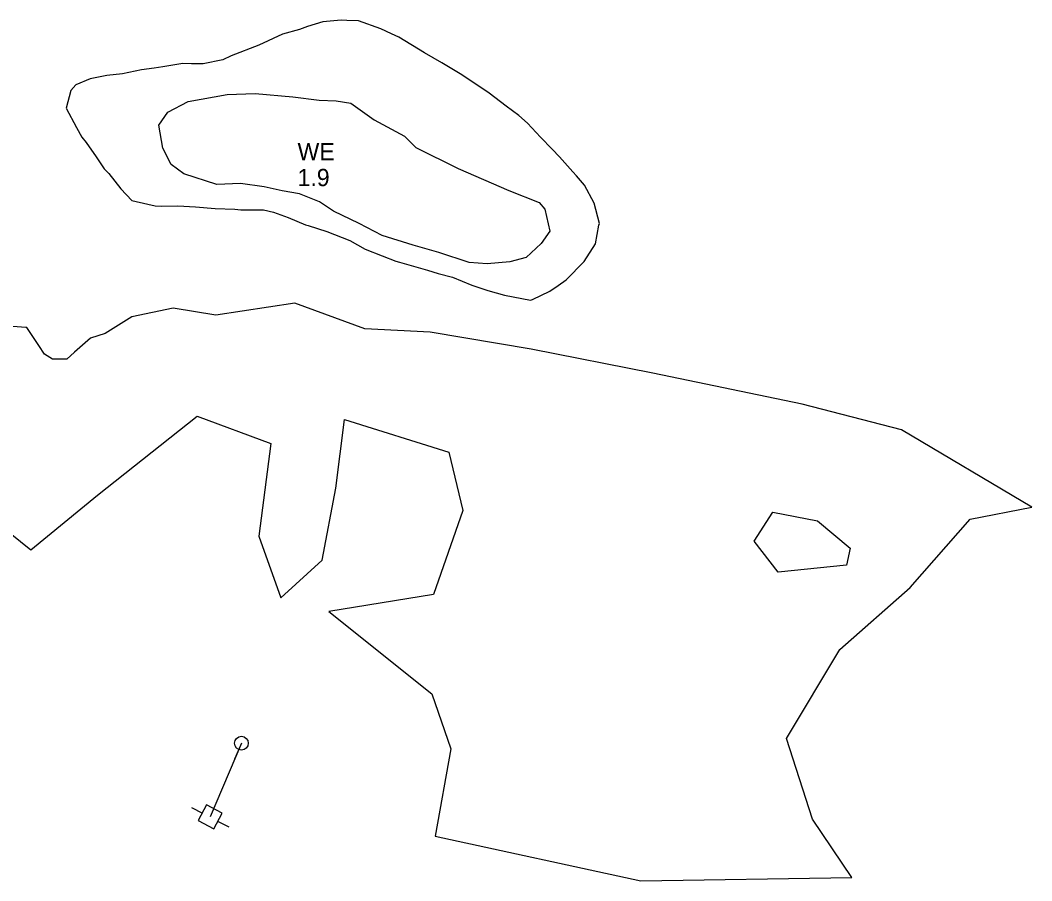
# Model space of a CAD drawing. Extents: x 2160437 to 2172832, y 205694 to 212444.
# Drawn here: x 2166777.9 to 2167070.9, y 209115.2 to 209364.4 of the extents above; entities that cross this region are included whole.
import ezdxf

# ---------------------------------------------------------------- set-up
doc = ezdxf.new("R2010")
doc.units = 0
for name, color, linetype in [('RD_EX_H2O_Pond', 7, 'Continuous'), ('RD_EX_H2O_txCode', 7, 'Continuous'), ('RD_EX_UT', 7, 'Continuous'), ('RD_EX_UT_Guy', 7, 'Continuous'), ('RD_EX_VEG_ShrubLine', 7, 'Continuous')]:
    doc.layers.add(name, color=color, linetype=linetype)

# ---------------------------------------------------------------- blocks, each defined once
blk = doc.blocks.new('PP')
at = {"layer": 'RD_EX_UT'}
for p, q in [((2.49, 2.51), (-2.51, 2.51)), ((-2.51, 2.51), (-2.51, -2.49)), ((2.49, -2.49), (2.49, 2.51)), ((-5.94, -0.05), (-2.47, -0.05)), ((-2.51, -2.49), (2.49, -2.49)), ((2.42, -0.05), (6.06, -0.05))]:
    blk.add_line(p, q, dxfattribs=at)

msp = doc.modelspace()

# ---------------------------------------------------------------- linework, layer by layer
at = {"layer": 'RD_EX_H2O_Pond'}
msp.add_lwpolyline([(2166869.39, 209341.06), (2166873.66, 209340.31), (2166880.39, 209335.51), (2166889.2, 209330.76), (2166892.44, 209327.48), (2166904.75, 209321.39), (2166919.46, 209315.08), (2166928.17, 209311.62), (2166929.84, 209309.68), (2166931.25, 209303.31), (2166928.79, 209299.69), (2166924.4, 209295.64), (2166919.73, 209294.4), (2166913.17, 209293.82), (2166907.95, 209294.26), (2166899.14, 209297.08), (2166891.75, 209299.19), (2166882.7, 209302.05), (2166876.03, 209305.46), (2166868.68, 209309.05), (2166864.62, 209311.76), (2166858.75, 209314.06), (2166853.79, 209314.94), (2166848.54, 209316.14), (2166841.75, 209317.1), (2166834.88, 209316.8), (2166825.32, 209319.89), (2166821.64, 209322.63), (2166819.18, 209327.36), (2166818.02, 209333.99), (2166820.62, 209337.79), (2166826.54, 209340.83), (2166837.82, 209342.88), (2166845.96, 209343.11), (2166856.83, 209342.22), (2166864.48, 209341.23)], close=True, dxfattribs=at)
at = {"layer": 'RD_EX_UT'}
msp.add_line((2166841.96, 209155), (2166839.96, 209150.42), dxfattribs=at)
msp.add_circle((2166841.96, 209155), 2, dxfattribs=at)
at = {"layer": 'RD_EX_UT_Guy'}
msp.add_lwpolyline([(2166841.96, 209155), (2166832.91, 209133.66)], dxfattribs=at)
at = {"layer": 'RD_EX_VEG_ShrubLine'}
for points in [[(2166846.98, 209357.16), (2166838.97, 209354.07), (2166836.58, 209352.91), (2166830.88, 209351.76), (2166827.53, 209351.79), (2166825.02, 209351.87), (2166819.26, 209350.87), (2166816.71, 209350.47), (2166813.02, 209350.03), (2166807.56, 209348.83), (2166803.03, 209348.33), (2166798.17, 209347.37), (2166793.97, 209345.66), (2166792.56, 209344.06), (2166791.25, 209338.86), (2166794.17, 209333.35), (2166795.75, 209330.52), (2166797.05, 209328.99), (2166799.95, 209324.81), (2166802.21, 209321.29), (2166803.61, 209319.97), (2166807.02, 209315.55), (2166810.27, 209312.15), (2166811.45, 209311.86), (2166816.96, 209310.67), (2166818.71, 209310.56), (2166823.56, 209310.66), (2166828.72, 209310.37), (2166828.72, 209310.37), (2166834.35, 209309.87), (2166840.1, 209309.63), (2166841.78, 209309.49), (2166848.36, 209309.43), (2166851.25, 209308.8), (2166855.47, 209307.26), (2166860.5, 209305.16), (2166861.32, 209304.91), (2166866.72, 209303.21), (2166873.37, 209300.56), (2166873.37, 209300.56), (2166877.8, 209298.11), (2166882.69, 209296.14), (2166886.71, 209294.56), (2166887.77, 209294.27), (2166895.88, 209291.96), (2166898.96, 209291.06), (2166903.08, 209289.99), (2166908.75, 209287.67), (2166913.33, 209286.09), (2166918.16, 209284.77), (2166925.67, 209283.35), (2166926.28, 209283.45), (2166931.31, 209285.89), (2166933.69, 209287.56), (2166936.04, 209289.17), (2166941.2, 209294.49), (2166944.54, 209299.64), (2166944.54, 209299.64), (2166945.53, 209304.98), (2166945.66, 209305.55), (2166944.15, 209311.41), (2166944.15, 209311.41), (2166941.34, 209316.61), (2166939, 209319.29), (2166938, 209320.49), (2166934.1, 209324.82), (2166931.99, 209327.02), (2166928.58, 209330.5), (2166924.8, 209334.52), (2166922.28, 209336.79), (2166918.6, 209339.52), (2166913.74, 209343.22), (2166913.74, 209343.22), (2166909.6, 209346.04), (2166905.28, 209348.88), (2166899.98, 209352.03), (2166899.98, 209352.03), (2166895, 209354.92), (2166887.54, 209359.49), (2166885.4, 209360.4), (2166882.33, 209361.85), (2166875.89, 209364.15), (2166872.48, 209364.33), (2166870.88, 209364.37), (2166865.57, 209363.92), (2166861.15, 209362.56), (2166858.77, 209361.71), (2166853.85, 209360.33)], [(2166995.91, 209221.91), (2167008.82, 209219.42), (2167018.25, 209211.48), (2167017.26, 209206.52), (2166997.4, 209204.53), (2166990.45, 209213.47)]]:
    msp.add_lwpolyline(points, close=True, dxfattribs=at)
msp.add_lwpolyline([(2166766.89, 209222.27), (2166780.95, 209210.98), (2166800.31, 209226.87), (2166829.11, 209249.71), (2166850.45, 209241.76), (2166846.98, 209214.96), (2166853.43, 209197.08), (2166865.35, 209208.01), (2166869.32, 209228.86), (2166871.8, 209248.71), (2166902.08, 209239.28), (2166906.05, 209222.4), (2166897.62, 209198.08), (2166867.33, 209193.11), (2166897.12, 209169.28), (2166902.58, 209153.4), (2166898.11, 209128.08), (2166957.68, 209115.17), (2167018.75, 209116.16), (2167007.33, 209133.04), (2166999.88, 209156.38), (2167015.27, 209182.19), (2167035.63, 209200.06), (2167053, 209219.92), (2167070.87, 209223.4), (2167033.14, 209245.74), (2167004.35, 209253.18), (2166961.16, 209262.12), (2166925.91, 209269.07), (2166896.62, 209274.03), (2166877.76, 209275.03), (2166857.4, 209282.47), (2166834.57, 209279), (2166822.16, 209280.98), (2166810.24, 209278.5), (2166802.54, 209273.67), (2166798.3, 209272.27), (2166793.66, 209268.24), (2166791.44, 209266.24), (2166787.22, 209266.21), (2166784.98, 209267.64), (2166783.26, 209270.22), (2166779.84, 209275.43), (2166779.52, 209275.39), (2166774.51, 209275.73)], dxfattribs=at)

# ---------------------------------------------------------------- block references
at = {"layer": 'RD_EX_UT', "xscale": 1.0199999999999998, "yscale": 1.02, "rotation": -27.660145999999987}
msp.add_blockref('PP', (2166832.91, 209133.66), dxfattribs=at)

# ---------------------------------------------------------------- texts
at = {"layer": 'RD_EX_H2O_txCode'}
for s, p in [('WE', (2166858.23, 209323.83)), ('1.9', (2166858.23, 209316.33))]:
    msp.add_text(s, height=5, dxfattribs=at).set_placement(p)

doc.saveas('drawing.dxf')
